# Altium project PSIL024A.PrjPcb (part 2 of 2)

## Sheet PSIL024A_sch3.SchDoc
size 431 x 279 mm; Date: Not shown in title block; ApprovedBy: Not shown in title block; CheckedBy: Not shown in title block; Author: Not shown in title block; CompanyName: Not shown in title block; Engineer: Not shown in title block; Organization: Not shown in title block; Address1: Not shown in title block; Address2: Not shown in title block; Address3: Not shown in title block; Address4: Not shown in title block; DocumentNumber: 1; Revision: Use project parameter SCH_Rev; SheetNumber: 3; SheetTotal: 4; PageSetup: Record=PageOptions¦CenterHorizontal=True¦CenterVertical=True¦PrintScale=1.00¦XCorrection=1.00¦YCorrection=1.00¦PrintKind=0¦BorderSize=5000000¦LeftOffset=0¦BottomOffset=0¦Orientation=2¦PaperLength=1000¦PaperWidth=1000¦Scale=100¦PaperSource=15¦PrintQuality=600¦MediaType=1¦DitherType=10¦PaperKind=Letter¦PrintScaleMode=1
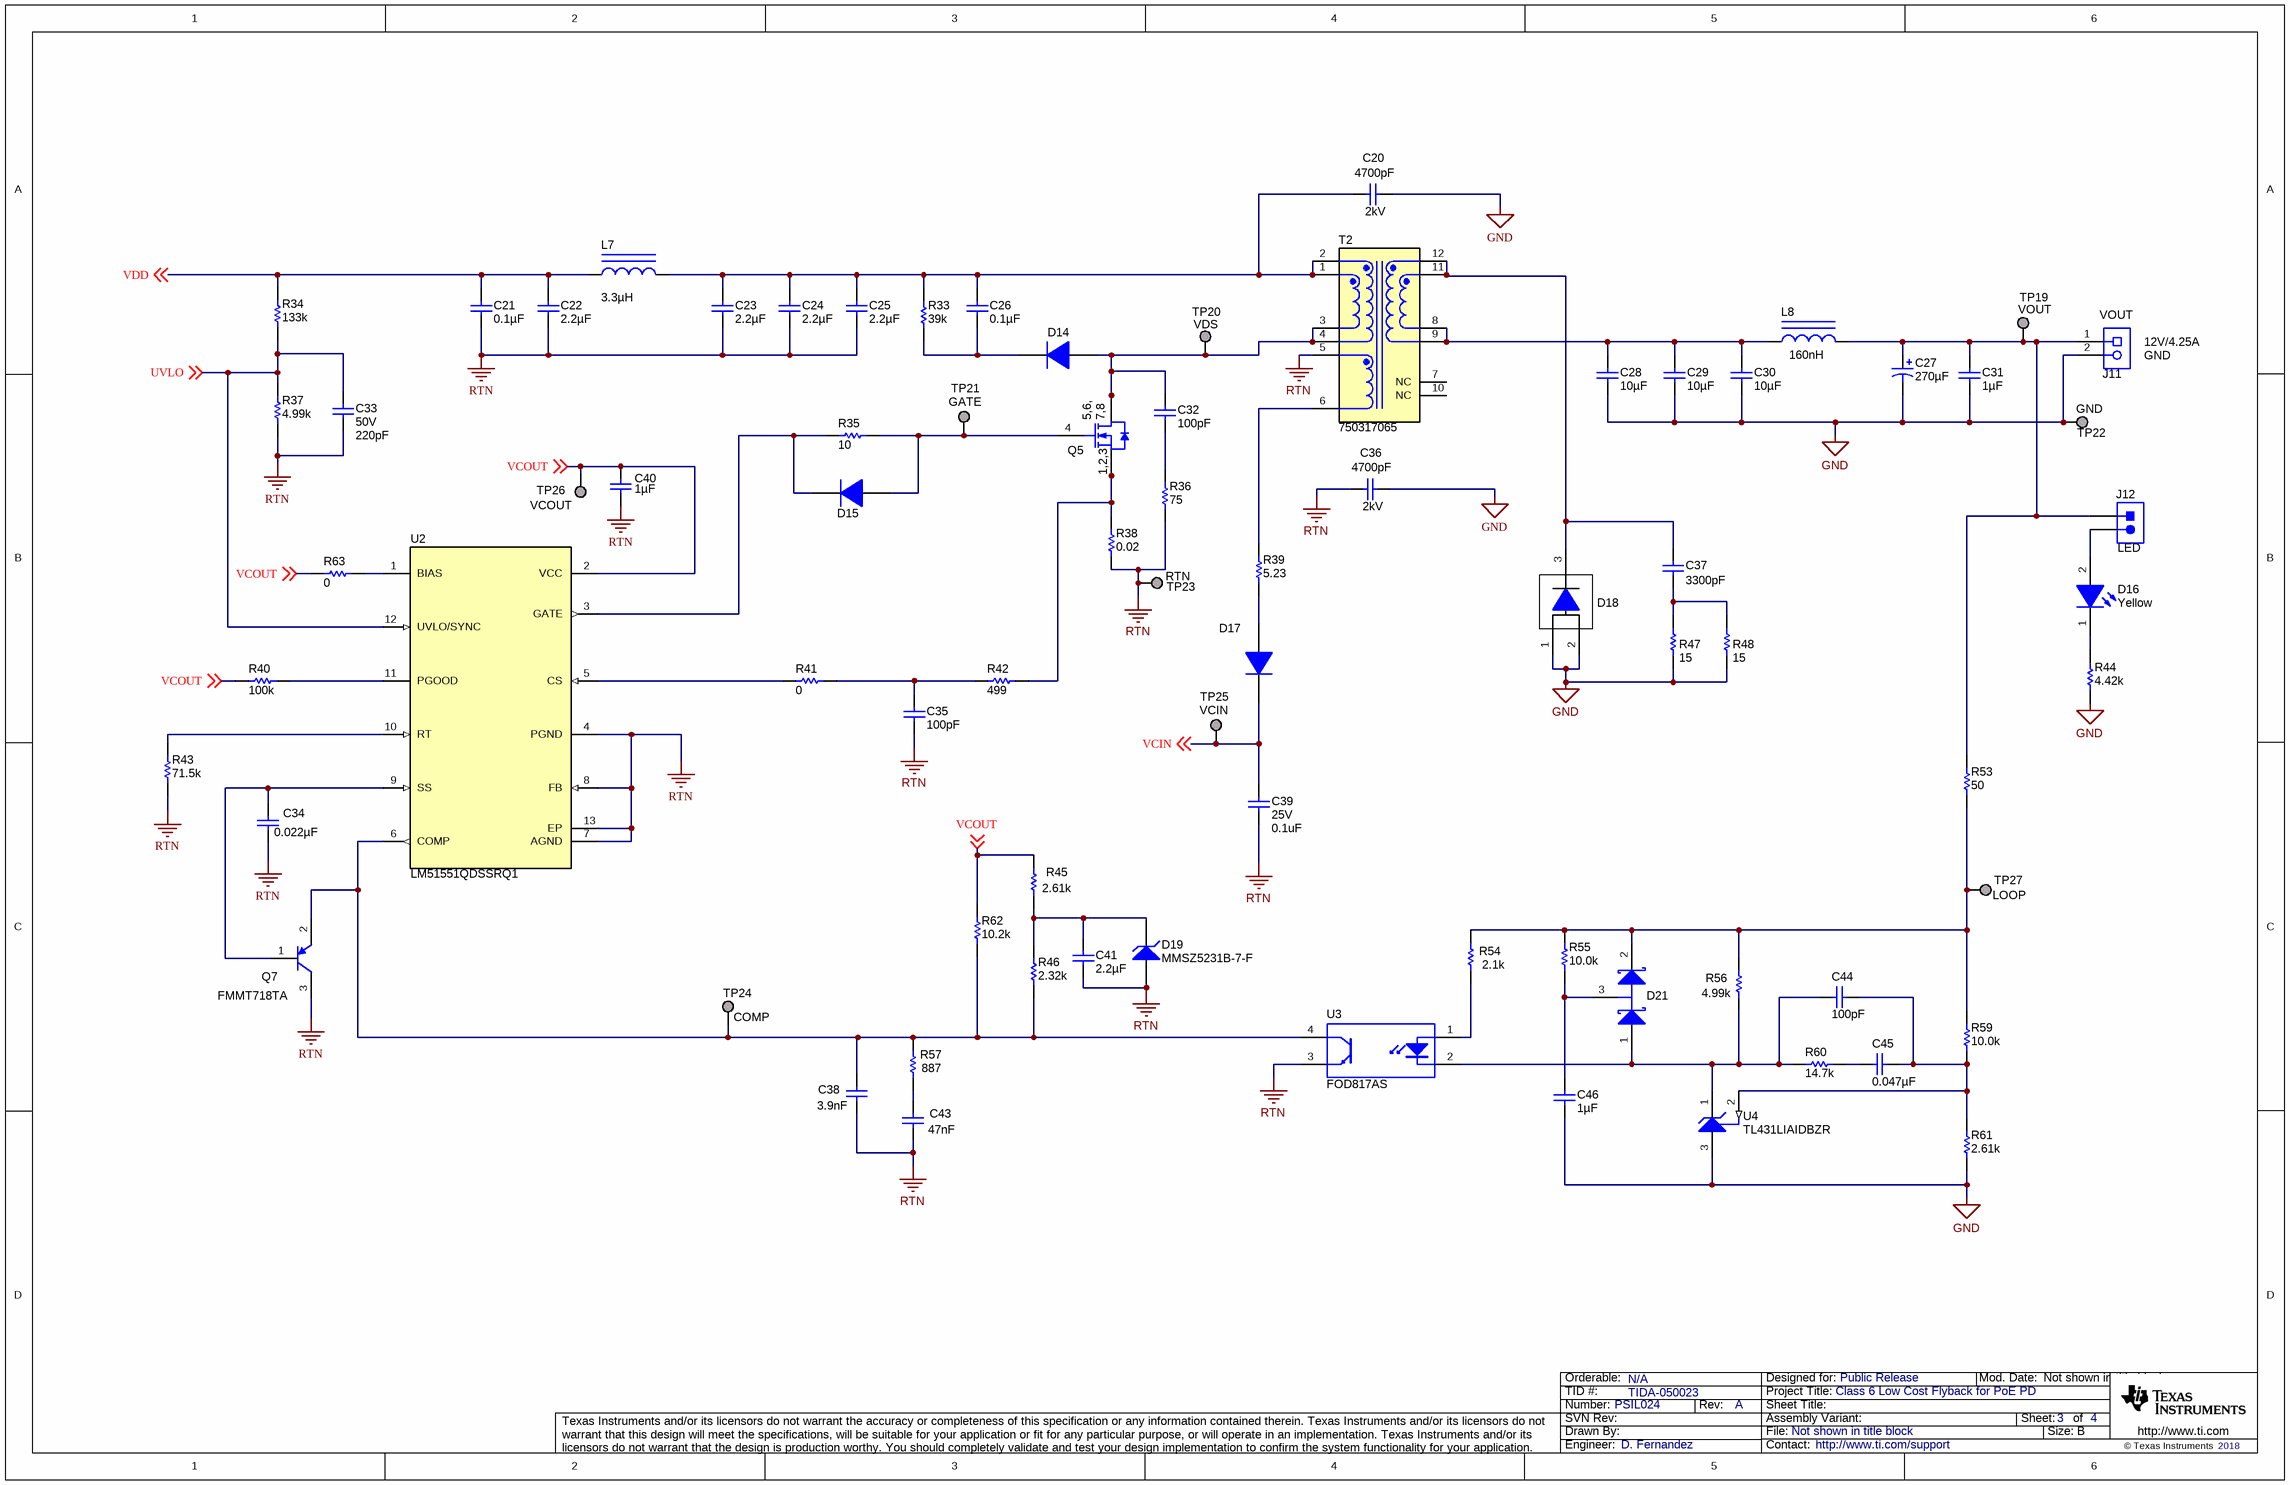
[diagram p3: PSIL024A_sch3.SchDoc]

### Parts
C20  VDC_V: 2kV  ValueDisplayed: 4700pF  [1812_254]  (hidden comment: 1812GC472KAT1A)
C21  ValueDisplayed: 0.1µF  [0805_HV]  (hidden comment: C2012X7R2A104K125AA)
C22  ValueDisplayed: 2.2µF  [1210_270]  (hidden comment: GRM32ER72A225KA35L)
C23  ValueDisplayed: 2.2µF  [1210_270]  (hidden comment: GRM32ER72A225KA35L)
C24  ValueDisplayed: 2.2µF  [1210_270]  (hidden comment: GRM32ER72A225KA35L)
C25  ValueDisplayed: 2.2µF  [1210_270]  (hidden comment: GRM32ER72A225KA35L)
C26  ValueDisplayed: 0.1µF  [0805_HV]  (hidden comment: C2012X7R2A104K125AA)
C27  ValueDisplayed: 270µF  [PCV_1000x1270]  (hidden comment: PCV1E271MCL1GS)
C28  ValueDisplayed: 10µF  [1210_280]  (hidden comment: C1210C106K3RACTU)
C29  ValueDisplayed: 10µF  [1210_280]  (hidden comment: C1210C106K3RACTU)
C30  ValueDisplayed: 10µF  [1210_280]  (hidden comment: C1210C106K3RACTU)
C31  ValueDisplayed: 1µF  [0805_HV]  (hidden comment: GRM21BR71E105KA99L)
C32  ValueDisplayed: 100pF  [0805_HV]  (hidden comment: GRM21A5C2E101JW01D)
C33  VDC_V: 50V  ValueDisplayed: 220pF  [0603L]  (hidden comment: C0603C221J5GACTU)
C34  ValueDisplayed: 0.022µF  [0603]  (hidden comment: C0603C223K3RACTU)
C35  ValueDisplayed: 100pF  [0603L]  (hidden comment: GRM1885C1H101JA01D)
C36  VDC_V: 2kV  ValueDisplayed: 4700pF  [1812_254]  (hidden comment: 1812GC472KAT1A)
C37  ValueDisplayed: 3300pF  [0603]  (hidden comment: 001)
C38  Cap_F: 3.9nF  [0603L]  (hidden comment: GRM1885C1H392JA01D)
C39  VDC_V: 25V  ValueDisplayed: 0.1uF  [0603]  (hidden comment: 06033C104JAT2A)
C40  ValueDisplayed: 1µF  [0805_HV]  (hidden comment: GRM21BR71E105KA99L)
C41  Cap_F: 2.2µF  [0603]  (hidden comment: EMK107BB7225KA-T)
C43  Cap_F: 47nF  [0603]  (hidden comment: 06033C473JAT2A)
C44  ValueDisplayed: 100pF  [0603L]  (hidden comment: GRM1885C1H101JA01D)
C45  ValueDisplayed: 0.047µF  [0603L]  (hidden comment: C1608X7R1H473K080AA)
C46  ValueDisplayed: 1µF  [0805L]  (hidden comment: GRM21BR71E105KA99L)
D14  ES2DA-13-F  [SMA]  (value not drawn)
D15  MMSD4148T1G  [SOD-123]  (value not drawn)
D16  value Yellow  [WL-SMCW_YELLOW]  (hidden comment: 150060YS75000)
D17  MMSD4148T1G  [SOD-123]  (value not drawn)
D18  001  [PowerDI5]  (value not drawn)
D19  MMSZ5231B-7-F  [SOD-123]
D21  BAT54S-7-F  [SOT-23]  (value not drawn)
J11  ED555/2DS  [TERM_BLK_ED555-2DS]  (value not drawn)
J12  LED  [Molex_87898-0204]
L7  ValueDisplayed: 3.3µH  [XFL4020]  (hidden comment: XFL4020-332MEB)
L8  Ind_H: 160nH  [XAL5030]  (hidden comment: XAL5030-161MEB)
Q5  FDMS86252  [TRANS_Fairchild_PQFN08A]  (value not drawn)
Q7  FMMT718TA  [SOT-23]
R33  ValueDisplayed: 39k  [1206]  (hidden comment: CRCW120639K0JNEA)
R34  133k  [0603]
R35  ValueDisplayed: 10  [0603]  (hidden comment: CRCW060310R0JNEA)
R36  ValueDisplayed: 75  [2010L]  (hidden comment: CRCW201075R0JNEF)
R37  ValueDisplayed: 4.99k  [0603]  (hidden comment: RT0603DRE074K99L)
R38  ValueDisplayed: 0.02  [2010]  (hidden comment: CSRN2010FK20L0)
R39  ValueDisplayed: 5.23  [0805_HV]  (hidden comment: CRCW08055R23FKEA)
R40  100k  [0603]
R41  ValueDisplayed: 0  [0603]  (hidden comment: MCR03EZPJ000)
R42  499  [0603]
R43  71.5k  [0603]
R44  ValueDisplayed: 4.42k  [0603]  (hidden comment: CRCW06034K42FKEA)
R45  Res_ohm: 2.61k  [0603]  (hidden comment: CRCW06032K61FKEA)
R46  Res_ohm: 2.32k  [0603]  (hidden comment: CRCW06032K32FKEA)
R47  ValueDisplayed: 15  [2512]  (hidden comment: 001)
R48  ValueDisplayed: 15  [2512]  (hidden comment: 001)
R53  ValueDisplayed: 50  [0603]  (hidden comment: CRCW060350R0FKEA)
R54  Res_ohm: 2.1k  [0603L]  (hidden comment: CRCW06032K10FKEA)
R55  ValueDisplayed: 10.0k  [0603L]  (hidden comment: CRCW060310K0FKEA)
R56  ValueDisplayed: 4.99k  [0603L]  (hidden comment: CRCW06034K99FKEA)
R57  Res_ohm: 887  [0603]  (hidden comment: CRCW0603887RFKEA)
R59  ValueDisplayed: 10.0k  [0603L]  (hidden comment: CRCW060310K0FKEA)
R60  ValueDisplayed: 14.7k  [0603]  (hidden comment: CRCW060314K7FKEA)
R61  ValueDisplayed: 2.61k  [0603L]  (hidden comment: CRCW06032K61FKEA)
R62  ValueDisplayed: 10.2k  [0603L]  (hidden comment: CRCW060310K2FKEA)
R63  ValueDisplayed: 0  [0603]  (hidden comment: MCR03EZPJ000)
T2  750317065  [Wurth_EFD25_4476]
TP19  VOUT  [Keystone_5019]
TP20  TESTPOINT  [Keystone_5019]  (value not drawn)
TP21  TESTPOINT  [Keystone_5019]  (value not drawn)
TP22  TESTPOINT  [Keystone_5019]  (value not drawn)
TP23  TESTPOINT  [Keystone_5019]  (value not drawn)
TP24  COMP  [Keystone_5019]
TP25  TESTPOINT  [Keystone_5019]  (value not drawn)
TP26  VCOUT  [Keystone_5019]
TP27  TESTPOINT  [Keystone_5019]  (value not drawn)
U2  LM51551QDSSRQ1  [DSS0012C]
U3  FOD817AS  [N04C]
U4  TL431LIAIDBZR  [DBZ0003A_M]

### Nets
GND: C20.1 C27.2(-) C28.2 C29.2 C30.2 C31.2 C36.1 C46.2 D18.1(A) D18.2(A) J11.2 R44.1 R47.1 R48.1 R61.1 TP22.1 U4.3(ANODE)
RTN: C21.1 C22.2 C23.2 C24.2 C25.2 C33.2 C34.2 C35.2 C36.2 C38.2 C39.2 C40.2 C41.2 C43.2 D19.2(A) Q7.3(C) R36.1 R37.1 R38.1 R43.1 T2.5 TP23.1 U2.4(PGND) U2.7(AGND) U2.8(FB) U2.13(EP) U3.3(E)
UVLO: C33.1 R34.1 R37.2 U2.12(UVLO/SYNC) ; off-sheet UVLO
VCIN: C39.1 D17.1(K) TP25.1 ; off-sheet VCIN
VCOUT: C40.1 R40.1 R45.2 R62.2 R63.1 TP26.1 U2.2(VCC) ; off-sheet VCOUT
VDD: C21.2 C22.1 L7.1 R34.2 ; off-sheet VDD
NetC20_2: C20.2 C23.1 C24.1 C25.1 C26.2 L7.2 R33.2 T2.1 T2.2
NetC26_1: C26.1 D14.1(K) R33.1
NetC27_1: C27.1(+) C31.1 J11.1 J12.1 L8.2 R53.2 TP19.1
NetC28_1: C28.1 C29.1 C30.1 L8.1 T2.8 T2.9
NetC32_1: C32.1 D14.2(A) Q5.5(D) Q5.6(D) Q5.7(D) Q5.8(D) T2.3 T2.4 TP20.1
NetC32_2: C32.2 R36.2
NetC34_1: C34.1 Q7.1(B) U2.9(SS)
NetC35_1: C35.1 R41.2 R42.1
NetC37_1: C37.1 D18.3(K) T2.11 T2.12
NetC37_2: C37.2 R47.2 R48.2
NetC38_1: C38.1 Q7.2(E) R46.1 R57.2 R62.1 TP24.1 U2.6(COMP) U3.4(C)
NetC41_1: C41.1 D19.1(K) R45.1 R46.2
NetC43_1: C43.1 R57.1
NetC44_1: C44.1 C45.1 R59.1 R61.2 U4.2(REF)
NetC44_2: C44.2 D21.1(A) R56.1 R60.1 U3.2(K) U4.1(CATHODE)
NetC45_2: C45.2 R60.2
NetC46_1: C46.1 D21.3(C) R55.1
NetD15_1: D15.1(K) R35.1 U2.3(GATE)
NetD15_2: D15.2(A) Q5.4(G) R35.2 TP21.1
NetD16_1: D16.1(K) R44.2
NetD16_2: D16.2(A) J12.2
NetD17_2: D17.2(A) R39.1
NetD21_2: D21.2(K) R53.1 R54.2 R55.2 R56.2 R59.2 TP27.1
NetQ5_1: Q5.1(S) Q5.2(S) Q5.3(S) R38.2 R42.2
NetR39_2: R39.2 T2.6
NetR40_2: R40.2 U2.11(PGOOD)
NetR41_1: R41.1 U2.5(CS)
NetR43_2: R43.2 U2.10(RT)
NetR54_1: R54.1 U3.1(A)
NetR63_2: R63.2 U2.1(BIAS)

Not connected (* = marked no-connect by the designer): T2 7(NC) 10(NC)

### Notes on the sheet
- (near TP20) VDS
- (near J11) VOUT
- (near J11) 12V/4.25A
- (near J11) GND
- (near TP21) GATE
- (near TP22) GND
- (near TP23) RTN
- (near TP25) VCIN
- (near TP27) LOOP

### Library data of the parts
C20 C36 = CMP-0009295-2: CAP, CERM, 4700 pF, 2000 V, +/- 10%, X7R, 1812; Manufacturer: AVX; TaMin_C: -55°C; Polarized: N; SizeAreaWB_mm2: 23.1; Value1: Unknown; U/M: EA; Value: 4700pF; TaMax_C: 125°C; SizeZ_mm: 2.54; SizeX_mm: 4.5; SizeY_mm: 3.2; Cap_Case: 1812; Value2: 2000V; SizeArea_mm2: 14.4; Cap_F: 4.7nF; AEC Category: Q200
C21 C26 = C2012X7R2A104K125AA: CAP, CERM, 0.1 µF, 100 V, +/- 10%, X7R, 0805; Manufacturer: TDK; Polarized: N; CompType: Capacitor; Value: 0.1uF; U/M: EA; Cap_F: 0.0000001; Tolerance_%: 10; ESR_ohm: 0.020726; Value1: 0.020726 ohm; VDC_V: 100; Value2: 100V; IRMS_A: 1.456; TaMin_C: -55; TaMax_C: 125; Cap_Case: 0805; SizeArea_mm2: 2.5; SizeAreaWB_mm2: 6.75; SizeX_mm: 2; SizeY_mm: 1.25; SizeZ_mm: 1.45; AEC Category: Q200
C22-C25 = GRM32ER72A225KA35L: CAP, CERM, 2.2 µF, 100 V, +/- 10%, X7R, 1210; Manufacturer: MuRata; Polarized: N; CompType: Capacitor; Value: 2.2uF; U/M: EA; Cap_F: 0.0000022; Tolerance_%: 10; ESR_ohm: 0.007; Value1: 0.007 ohm; VDC_V: 100; Value2: 100V; IRMS_A: 4.4; TaMin_C: -55; TaMax_C: 125; Cap_Case: 1210; SizeArea_mm2: 8; SizeAreaWB_mm2: 14.7; SizeX_mm: 3.2; SizeY_mm: 2.5; SizeZ_mm: 2.7; AEC Category: Q200
C27 = PCV1E271MCL1GS: CAP, Aluminum Polymer, 270 µF, 25 V,+/- 20%, 0.027 ohm, D10xL12.7mm SMD; Manufacturer: Nichicon; Polarized: Y; CompType: Capacitor; Value: 270uF; U/M: EA; Cap_F: 0.00027; Tolerance_%: 20; VDC_V: 25; Value2: 25V; ESR_ohm: 0.027; IRMS_A: 2.7; TaMin_C: -55; TaMax_C: 105; Cap_Case: 10x12.7mm; SizeAreaWB_mm2: 144; SizeArea_mm2: 100; SizeX_mm: 10; SizeZ_mm: 12.7; AEC Category: Q200; AEC Qualified: N; Green_Lifecycle: Active; Green_REACh: Passed
C28-C30 = C1210C106K3RACTU: CAP, CERM, 10 µF, 25 V, +/- 10%, X7R, 1210; Manufacturer: Kemet; Polarized: N; CompType: Capacitor; Value: 10uF; U/M: EA; Cap_F: 0.00001; Tolerance_%: 10; Value1: Unknown; VDC_V: 25; Value2: 25V; TaMin_C: -55; TaMax_C: 125; Cap_Case: 1210; SizeArea_mm2: 8; SizeAreaWB_mm2: 14.7; SizeX_mm: 3.2; SizeY_mm: 2.5; SizeZ_mm: 2.8; AEC Category: Q200
C31 C40 C46 = GRM21BR71E105KA99L: CAP, CERM, 1 µF, 25 V, +/- 10%, X7R, 0805; Manufacturer: MuRata; Polarized: N; CompType: Capacitor; Value: 1uF; U/M: EA; Cap_F: 0.000001; Tolerance_%: 10; Value1: Unknown; VDC_V: 25; Value2: 25V; TaMin_C: -55; TaMax_C: 125; Cap_Case: 0805; SizeArea_mm2: 2.5; SizeAreaWB_mm2: 6.75; SizeX_mm: 2; SizeY_mm: 1.25; SizeZ_mm: 1.45; AEC Category: Q200
C32 = GRM21A5C2E101JW01D: CAP, CERM, 100 pF, 250 V, +/- 5%, C0G/NP0, 0805; Manufacturer: MuRata; Polarized: N; CompType: Capacitor; Value: 100pF; U/M: EA; Cap_F: 0.0000000001; Tolerance_%: 5; Value1: Unknown; VDC_V: 250; Value2: 250V; TaMin_C: -55; TaMax_C: 125; Cap_Case: 0805; SizeArea_mm2: 2.5; SizeAreaWB_mm2: 6.75; SizeX_mm: 2; SizeY_mm: 1.25; SizeZ_mm: 1.45; AEC Category: Q200
C33 = CMP-0006893-4: CAP, CERM, 220 pF, 50 V, +/- 5%, C0G/NP0, 0603; Manufacturer: Kemet; TaMin_C: -55°C; Polarized: N; SizeAreaWB_mm2: 4.68; Value1: Unknown; U/M: EA; Value: 220pF; TaMax_C: 125°C; SizeZ_mm: 1; SizeX_mm: 1.6; SizeY_mm: 0.8; Cap_Case: 0603; SizeArea_mm2: 1.28; CompType: Capacitor; AEC Category: Q200
C34 = C0603C223K3RACTU: CAP, CERM, 0.022 µF, 25 V,+/- 10%, X7R, 0603; Manufacturer: Kemet; Polarized: N; CompType: Capacitor; Value: 0.022uF; U/M: EA; Cap_F: 0.000000022; Tolerance_%: 10; VDC_V: 25; Value2: 25V; TaMin_C: -55; TaMax_C: 125; SizeArea_mm2: 1.28; SizeAreaWB_mm2: 4.68; SizeX_mm: 1.6; SizeY_mm: 0.8; SizeZ_mm: 1; AEC Category: Q200; Green_Lifecycle: Active; Green_REACh: Passed
C35 C44 = GRM1885C1H101JA01D: CAP, CERM, 100 pF, 50 V, +/- 5%, C0G/NP0, 0603; Manufacturer: MuRata; Polarized: N; CompType: Capacitor; Value: 100pF; U/M: EA; Cap_F: 0.0000000001; Tolerance_%: 5; Value1: Unknown; VDC_V: 50; Value2: 50V; TaMin_C: -55; TaMax_C: 125; Cap_Case: 0603; SizeArea_mm2: 1.28; SizeAreaWB_mm2: 4.68; SizeX_mm: 1.6; SizeY_mm: 0.8; SizeZ_mm: 1; AEC Category: Q200
C37 = GRM188R72A332KA01D: CAP, CERM, 3300 pF, 100 V, +/- 10%, X7R, 0603; Manufacturer: MuRata; Polarized: N; CompType: Capacitor; Value: 3300pF; U/M: EA; Cap_F: 0.0000000033; Tolerance_%: 10; Value1: Unknown; VDC_V: 100; Value2: 100V; TaMin_C: -55; TaMax_C: 125; SizeArea_mm2: 1.28; SizeAreaWB_mm2: 4.68; SizeX_mm: 1.6; SizeY_mm: 0.8; SizeZ_mm: 1; AEC Category: Q200
C38 = CMP-0007216-4: CAP, CERM, 3900 pF, 50 V, +/- 5%, C0G/NP0, 0603; Manufacturer: MuRata; TaMin_C: -55°C; Polarized: N; SizeAreaWB_mm2: 4.68; Value1: Unknown; U/M: EA; Value: 3900pF; TaMax_C: 125°C; SizeZ_mm: 1; SizeX_mm: 1.6; SizeY_mm: 0.8; Cap_Case: 0603; Value2: 50V; SizeArea_mm2: 1.28; CompType: Capacitor; AEC Category: Q200
C39 = CMP-0006752-5: CAP, CERM, 0.1 uF, 25 V, +/- 5%, X7R, 0603; Manufacturer: AVX; TaMin_C: -55°C; ESR_ohm: 0.05; Polarized: N; SizeAreaWB_mm2: 4.68; Value1: 0.05 ohm; U/M: EA; Value: 0.1uF; TaMax_C: 125°C; SizeZ_mm: 1; SizeX_mm: 1.6; SizeY_mm: 0.8; SizeArea_mm2: 1.28; Cap_F: 100nF; AEC Category: Q200
C41 = CMP-0007121-4: CAP, CERM, 2.2 uF, 16 V, +/- 10%, X7R, 0603; Manufacturer: Taiyo Yuden; TaMin_C: -55°C; Polarized: N; SizeAreaWB_mm2: 4.68; Value1: Unknown; U/M: EA; Value: 2.2uF; TaMax_C: 125°C; SizeZ_mm: 1; SizeX_mm: 1.6; SizeY_mm: 0.8; Value2: 16V; SizeArea_mm2: 1.28; CompType: Capacitor; AEC Category: Q200
C43 = CMP-0006757-5: CAP, CERM, 0.047 uF, 25 V, +/- 5%, X7R, 0603; Manufacturer: AVX; Polarized: N; CompType: Capacitor; U/M: EA; ESR_ohm: 0.052; Value1: 0.052 ohm; VDC_V: 25V; TaMin_C: -55°C; TaMax_C: 125°C; SizeArea_mm2: 1.28; SizeAreaWB_mm2: 4.68; SizeX_mm: 1.6; SizeY_mm: 0.8; SizeZ_mm: 1; AEC Category: Q200
C45 = C1608X7R1H473K080AA: CAP, CERM, 0.047 µF, 50 V, +/- 10%, X7R, 0603; Manufacturer: TDK; Polarized: N; CompType: Capacitor; Value: 0.047uF; U/M: EA; Cap_F: 0.000000047; Tolerance_%: 10; ESR_ohm: 0.049007; Value1: 0.049007 ohm; VDC_V: 50; Value2: 50V; IRMS_A: 0.767528; TaMin_C: -55; TaMax_C: 125; Cap_Case: 0603; SizeArea_mm2: 1.28; SizeAreaWB_mm2: 4.68; SizeX_mm: 1.6; SizeY_mm: 0.8; SizeZ_mm: 1; AEC Category: Q200
D14 = ES2DA-13-F: Diode, Superfast Rectifier, 200 V, 2 A, SMA; Manufacturer: Diodes Inc.; U/M: EA; Vf_V: 0.92; Value: 200V; Value1: 2A; Value2: 0.92V; Io_A: 2; Vr_V: 200; TJmax_C: 150; RJC_CperW: 20; SizeAreaWB_mm2: 37.3428; SizeArea_mm2: 16.3228; SizeX_mm: 5.59; SizeY_mm: 2.92; SizeZ_mm: 2.87; AEC Category: Q101
D15 D17 = MMSD4148T1G: Diode, Switching, 100 V, 0.2 A, SOD-123; Manufacturer: ON Semiconductor; U/M: EA; Vf_V: 1; Value: 100V; Value1: 0.2A; Value2: 1V; Io_A: 0.2; Vr_V: 100; TJmax_C: 150; SizeAreaWB_mm2: 13.095; SizeArea_mm2: 6.545; SizeX_mm: 3.85; SizeY_mm: 1.7; SizeZ_mm: 1.35; AEC Category: Q101
D16 = 150060YS75000: LED, Yellow, SMD; Manufacturer: Wurth Elektronik; Type: AlInGaP; Vf_V: 2; Value2: 2V; Io_A: 0.02; Value1: W; U/M: EA; Green_Lifecycle: Active; Green_REACh: Passed
D18 = SBRT20U60SP5-7: Diode, Super Barrier Rectifier, 60 V, 20 A, AEC-Q101, PowerDI5; Manufacturer: Diodes Inc.; SymbolCreator: a0412235; U/M: EA; Vf_V: 0.53; Value: 60V; Value1: 20A; Value2: 0.53V; Io_A: 20; Vr_V: 60; TJmax_C: 150; SizeAreaWB_mm2: 49.56; SizeArea_mm2: 24.96; SizeX_mm: 6.4; SizeY_mm: 3.9; SizeZ_mm: 1.05; AEC Category: Q101; AEC Qualified: Y; Green_Lifecycle: Not Set; Green_REACh: Incomplete
D19 = CMP-0005802-3: Diode, Zener, 5.1 V, 500 mW, SOD-123; Manufacturer: Diodes Inc.; SizeAreaWB_mm2: 13.095; SizeX_mm: 3.85; SizeArea_mm2: 6.545; Power_W: 500mW; Vz_V: 5.1V; RJA_CperW: 350; AEC Category: Q101; SizeY_mm: 1.7; Value1: 0.5W; Value: 5.1V; SizeZ_mm: 1.35
D21 = BAT54S-7-F: Diode, Schottky, 30 V, 0.2 A, SOT-23; Manufacturer: Diodes Inc.; U/M: EA; Vf_V: 0.65; Value: 30V; Value1: 0.2A; Value2: 0.65V; Io_A: 0.2; Vr_V: 30; TJmax_C: 125; SizeAreaWB_mm2: 14; SizeArea_mm2: 7.5; SizeX_mm: 2.5; SizeY_mm: 3; SizeZ_mm: 1.1; AEC Category: Q101
J11 = ED555/2DS: Terminal Block, 3.5mm Pitch, 2x1, TH; Manufacturer: On-Shore Technology; SymbolCreator: a0412235; Pitch_mm: 3.5; Gender: Female; Shrouded: N; Row_Count: 1; ContactFinish: Brass; Current_A: 6; Voltage_V: 150; Cert_CULUS: Y
J12 = 87898-0204: Header, 2.54 mm, 2x1, Gold, R/A, SMT; Manufacturer: Molex; SymbolCreator: a0412235; Pitch_mm: 2.54; Gender: Male; Shrouded: N; Row_Count: 1
L7 = XFL4020-332MEB: Inductor, Shielded, Composite, 3.3 µH, 2.9 A, 0.03 ohm, SMD; Manufacturer: Coilcraft; Value: 3.3uH; Ind_H: 3.3E-6; Imax_A: 2.9; Irms: 5.2A @ 40C rise; Isat: 2.9A @ 30% inductance drop; DCR_ohm: 0.03; Value2: 2.9A; AEC Category: Q200
L8 = CMP-0061000-2: Inductor, Shielded, Composite, 160 nH, 22.2 A, 0.00215 ohm, AEC-Q200 Grade 1, SMD; Manufacturer: Coilcraft; Isat: 31A @ 30% inductance drop; Irms: 22.2A @ 40C rise; Green_Lifecycle: Not Set; SizeAreaWB_mm2: 54.4544; DCR_ohm: 2.15m; Green_REACh: Incomplete; Value: 160nH; Imax_A: 22.2A; SizeZ_mm: 3.1; SizeX_mm: 5.28; SizeY_mm: 5.48; SizeArea_mm2: 28.9344; AEC Qualified: 1; AEC Category: Q200; AEC Grade: Y
Q5 = FDMS86252: MOSFET, N-CH, 150 V, 4.6 A, PQFN08A; Manufacturer: Fairchild Semiconductor; Alternate Manufacturer: None; U/M: EA; ChType: N; Value: 150V; VdsMax_V: 150; Value1: 0.07 ohm; Rdson45_ohm: 0.07; Value2: 11 nC; QgTyp_nC: 11; Vgs_V: 20; IdsMax_A: 4.6; SizeAreaWB_mm2: 56; SizeArea_mm2: 30; SizeX_mm: 5; SizeY_mm: 6; SizeZ_mm: 1.1; AEC Category: Q101
Q7 = CMP-0000330-2: Transistor, PNP, 20 V, 1.5 A, SOT-23; Manufacturer: Diodes Inc.; TaMax_C: 150°C; Value2: 6; Value1: 1.5 A; Vcesat1_V: 20V; SizeX_mm: 2.5; SizeY_mm: 3; TaMin_C: -55°C; IcRated_A: 1.5A; CompType: BJT; SizeZ_mm: 1.1; Value: 20 V; SizeArea_mm2: 7.5; NPN: 0; PNP: 1; AEC Category: Q101; SizeAreaWB_mm2: 14; U/M: EA
R33 = CRCW120639K0JNEA: RES, 39 k, 5%, 0.25 W, 1206; Manufacturer: Vishay-Dale; CompType: Resistor; Value: 39k; Res_ohm: 39000; Value_Code: 39k0; Tolerance_%: 5; Power_W: 0.25; Value2: 0.25W; VDC_V: 200; TempCo: 200 ppm/C; SizeArea_mm2: 5.12; SizeX_mm: 3.2; SizeY_mm: 1.6; SizeZ_mm: 1.35; EIA_Code: E24; U/M: EA; AEC Category: Q200
R34 = CMP-0024655-3: RES, 133 k, 0.5%, 0.1 W, 0603; Manufacturer: Yageo America; PartNumber: RT0603DRE07133KL; Power_W: 100mW; TempCo: 50 ppm/C; U/M: EA; EIA_Code: E192; SizeX_mm: 1.6; SizeY_mm: 0.8; SizeZ_mm: 1; Value2: 0.1W; SizeArea_mm2: 1.28; CompType: Resistor; VDC_V: 75V; AEC Category: Q200
R35 = CMP-0025703-4: RES, 10, 5%, 0.1 W, AEC-Q200 Grade 0, 0603; Manufacturer: Vishay-Dale; Value: 10; Value_Code: 10R0; Power_W: 100mW; Value2: 0.1W; VDC_V: 75V; TempCo: 200 ppm/C; SizeArea_mm2: 1.28; SizeX_mm: 1.6; SizeY_mm: 0.8; SizeZ_mm: 1; EIA_Code: E24; AEC Category: Q200; AEC Qualified: Y; AEC Grade: 0
R36 = CRCW201075R0JNEF: RES, 75, 5%, 0.75 W, AEC-Q200 Grade 0, 2010; Manufacturer: Vishay-Dale; CompType: Resistor; Value: 75; Value_Code: 75R0; Tolerance_%: 5; Power_W: 0.75; Value2: 0.75W; VDC_V: 400; TempCo: 200 ppm/C; SizeArea_mm2: 12.5; SizeY_mm: 2.5; SizeZ_mm: 1.66; EIA_Code: E24; U/M: EA; AEC Category: Q200; AEC Qualified: Y; AEC Grade: 0
R37 = RT0603DRE074K99L: RES, 4.99 k, 0.5%, 0.1 W, 0603; Manufacturer: Yageo America; CompType: Resistor; Value: 4.99k; Res_ohm: 4990; Value_Code: 4k99; Tolerance_%: 0.5; Power_W: 0.1; Value2: 0.1W; VDC_V: 75; TempCo: 50 ppm/C; SizeArea_mm2: 1.28; SizeX_mm: 1.6; SizeY_mm: 0.8; SizeZ_mm: 1; EIA_Code: E192; U/M: EA; AEC Category: Q200; Green_Lifecycle: Active; Green_REACh: Passed
R38 = CSRN2010FK20L0: RES, 0.02, 1%, 1 W, 2010; Manufacturer: Stackpole Electronics Inc; CompType: Resistor; Value: 0.02; Value_Code: R020; Tolerance_%: 1; Value2: 1W; TempCo: 250 ppm/C; SizeArea_mm2: 12.5; SizeX_mm: 5; SizeY_mm: 2.5; SizeZ_mm: 1.66; EIA_Code: E96; U/M: EA; AEC Category: Q200
R39 = CRCW08055R23FKEA: RES, 5.23, 1%, 0.125 W, 0805; Manufacturer: Vishay-Dale; CompType: Resistor; Value: 5.23; Value_Code: 5R23; Tolerance_%: 1; Power_W: 0.125; Value2: 0.125W; VDC_V: 150; TempCo: 100 ppm/C; SizeArea_mm2: 2.5; SizeX_mm: 2; SizeY_mm: 1.25; SizeZ_mm: 1.45; EIA_Code: E96; U/M: EA; AEC Category: Q200
R40 = CMP-0021990-4: RES, 100 k, 1%, 0.1 W, AEC-Q200 Grade 0, 0603; Manufacturer: Vishay-Dale; PartNumber: CRCW0603100KFKEA; Power_W: 100mW; TempCo: 100 ppm/C; EIA_Code: E96; SizeX_mm: 1.6; SizeY_mm: 0.8; SizeZ_mm: 1; Value2: 0.1W; SizeArea_mm2: 1.28; CompType: Resistor; AEC Qualified: Y; VDC_V: 75V; AEC Category: Q200; AEC Grade: 0
R41 R63 = MCR03EZPJ000: RES, 0, 5%, 0.1 W, 0603; Manufacturer: Rohm; CompType: Resistor; Value: 0; Value_Code: 0000; Tolerance_%: 5; Power_W: 0.1; Value2: 0.1W; VDC_V: 50; TempCo: 400 ppm/C; SizeArea_mm2: 1.28; SizeX_mm: 1.6; SizeY_mm: 0.8; SizeZ_mm: 1; EIA_Code: E24; U/M: EA; AEC Category: Q200; AEC Qualified: N; Green_Lifecycle: Active; Green_REACh: Passed
R42 = CMP-0025330-3: RES, 499, 0.5%, 0.1 W, 0603; Manufacturer: Yageo America; PartNumber: RT0603DRE07499RL; Power_W: 100mW; TempCo: 50 ppm/C; Value_Code: 499R; U/M: EA; EIA_Code: E192; SizeX_mm: 1.6; SizeY_mm: 0.8; SizeZ_mm: 1; Value2: 0.1W; SizeArea_mm2: 1.28; CompType: Resistor; VDC_V: 75V; AEC Category: Q200
R43 = CMP-0025543-3: RES, 71.5 k, 0.5%, 0.1 W, 0603; Manufacturer: Yageo America; PartNumber: RT0603DRE0771K5L; Power_W: 100mW; TempCo: 50 ppm/C; Value_Code: 71k5; U/M: EA; EIA_Code: E192; SizeX_mm: 1.6; SizeY_mm: 0.8; SizeZ_mm: 1; Value2: 0.1W; SizeArea_mm2: 1.28; CompType: Resistor; VDC_V: 75V; AEC Category: Q200
R44 = CRCW06034K42FKEA: RES, 4.42 k, 1%, 0.1 W, 0603; Manufacturer: Vishay-Dale; CompType: Resistor; Value: 4.42k; Res_ohm: 4420; Value_Code: 4k42; Tolerance_%: 1; Power_W: 0.1; Value2: 0.1W; VDC_V: 75; TempCo: 100 ppm/C; SizeArea_mm2: 1.28; SizeX_mm: 1.6; SizeY_mm: 0.8; EIA_Code: E96; U/M: EA; AEC Category: Q200; Green_Lifecycle: Active; Green_REACh: Passed
R45 = CMP-0022279-4: RES, 2.61 k, 1%, 0.1 W, AEC-Q200 Grade 0, 0603; Manufacturer: Vishay-Dale; Power_W: 100mW; TempCo: 100 ppm/C; Value_Code: 2k61; Value: 2.61k; EIA_Code: E96; SizeX_mm: 1.6; SizeY_mm: 0.8; SizeZ_mm: 1; Value2: 0.1W; SizeArea_mm2: 1.28; CompType: Resistor; AEC Qualified: Y; VDC_V: 75V; AEC Category: Q200; AEC Grade: 0
R46 = CMP-0022274-4: RES, 2.32 k, 1%, 0.1 W, AEC-Q200 Grade 0, 0603; Manufacturer: Vishay-Dale; Power_W: 100mW; TempCo: 100 ppm/C; Value_Code: 2k32; Value: 2.32k; EIA_Code: E96; SizeX_mm: 1.6; SizeY_mm: 0.8; SizeZ_mm: 1; Value2: 0.1W; SizeArea_mm2: 1.28; CompType: Resistor; AEC Qualified: Y; VDC_V: 75V; AEC Category: Q200; AEC Grade: 0
R47 R48 = CRCW251215R0JNEG: RES, 15, 5%, 1 W, AEC-Q200 Grade 0, 2512; Manufacturer: Vishay-Dale; CompType: Resistor; Value: 15; Value_Code: 15R0; Tolerance_%: 5; Power_W: 1; Value2: 1W; VDC_V: 500; TempCo: 200 ppm/C; EIA_Code: E24; U/M: EA; SizeArea_mm2: 20.16; SizeX_mm: 6.3; SizeY_mm: 3.2; SizeZ_mm: 0.71; AEC Category: Q200; AEC Qualified: Y; AEC Grade: 0
R53 = CRCW060350R0FKEA: RES, 50, 1%, 0.1 W, 0603; Manufacturer: Vishay-Dale; CompType: Resistor; Value: 50; Value_Code: 50R0; Tolerance_%: 1; Power_W: 0.1; Value2: 0.1W; VDC_V: 75; TempCo: 100 ppm/C; SizeArea_mm2: 1.28; SizeX_mm: 1.6; SizeY_mm: 0.8; U/M: EA; AEC Category: Q200; Green_Lifecycle: Active; Green_REACh: Passed
R54 = CMP-0022270-4: RES, 2.10 k, 1%, 0.1 W, AEC-Q200 Grade 0, 0603; Manufacturer: Vishay-Dale; CompType: Resistor; Value: 2.10k; Value_Code: 2k10; Power_W: 100mW; Value2: 0.1W; VDC_V: 75V; TempCo: 100 ppm/C; SizeArea_mm2: 1.28; SizeX_mm: 1.6; SizeY_mm: 0.8; SizeZ_mm: 1; EIA_Code: E96; AEC Category: Q200; AEC Qualified: Y; AEC Grade: 0
R55 R59 = CRCW060310K0FKEA: RES, 10.0 k, 1%, 0.1 W, 0603; Manufacturer: Vishay-Dale; CompType: Resistor; Value: 10.0k; Res_ohm: 10000; Value_Code: 10k0; Tolerance_%: 1; Power_W: 0.1; Value2: 0.1W; VDC_V: 75; TempCo: 100 ppm/C; SizeArea_mm2: 1.28; SizeX_mm: 1.6; SizeY_mm: 0.8; EIA_Code: E96; U/M: EA; AEC Category: Q200
R56 = CRCW06034K99FKEA: RES, 4.99 k, 1%, 0.1 W, 0603; Manufacturer: Vishay-Dale; CompType: Resistor; Value: 4.99k; Res_ohm: 4990; Value_Code: 4k99; Tolerance_%: 1; Power_W: 0.1; Value2: 0.1W; VDC_V: 75; TempCo: 100 ppm/C; SizeArea_mm2: 1.28; SizeX_mm: 1.6; SizeY_mm: 0.8; EIA_Code: E96; U/M: EA; AEC Category: Q200
R57 = CMP-0022631-5: RES, 887, 1%, 0.1 W, AEC-Q200 Grade 0, 0603; Manufacturer: Vishay-Dale; CompType: Resistor; Value: 887; Value_Code: 887R; Power_W: 100mW; Value2: 0.1W; VDC_V: 75V; TempCo: 100 ppm/C; SizeArea_mm2: 1.28; SizeX_mm: 1.6; SizeY_mm: 0.8; SizeZ_mm: 1; EIA_Code: E96; AEC Category: Q200; AEC Qualified: Y; AEC Grade: 0
R60 = CRCW060314K7FKEA: RES, 14.7 k, 1%, 0.1 W, 0603; Manufacturer: Vishay-Dale; CompType: Resistor; Value: 14.7k; Res_ohm: 14700; Value_Code: 14k7; Tolerance_%: 1; Power_W: 0.1; Value2: 0.1W; VDC_V: 75; TempCo: 100 ppm/C; SizeArea_mm2: 1.28; SizeX_mm: 1.6; SizeY_mm: 0.8; EIA_Code: E96; U/M: EA; AEC Category: Q200; Green_Lifecycle: Active; Green_REACh: Passed
R61 = CRCW06032K61FKEA: RES, 2.61 k, 1%, 0.1 W, 0603; Manufacturer: Vishay-Dale; CompType: Resistor; Value: 2.61k; Res_ohm: 2610; Value_Code: 2k61; Tolerance_%: 1; Power_W: 0.1; Value2: 0.1W; VDC_V: 75; TempCo: 100 ppm/C; SizeArea_mm2: 1.28; SizeX_mm: 1.6; SizeY_mm: 0.8; EIA_Code: E96; U/M: EA; AEC Category: Q200
R62 = CMP-0021999-4: RES, 10.2 k, 1%, 0.1 W, AEC-Q200 Grade 0, 0603; Manufacturer: Vishay-Dale; Power_W: 100mW; TempCo: 100 ppm/C; Value_Code: 10k2; Value: 10.2k; EIA_Code: E96; SizeX_mm: 1.6; SizeY_mm: 0.8; SizeZ_mm: 1; Value2: 0.1W; SizeArea_mm2: 1.28; AEC Qualified: Y; VDC_V: 75V; AEC Category: Q200; AEC Grade: 0
T2 = CMP-0077631-2: Transformer, 30 uH, SMT; Manufacturer: Wurth Elektronik; SizeAreaWB_mm2: 1000.0835; SizeArea_mm2: 877.1235; AEC Qualified: N; Lp: 30; AEC Category: Q200; Value: 30uH; SizeZ_mm: 13.97; Ind_H: 30µH; SizeY_mm: 27.03; Ns1toNp: 0.375; Rsec1_ohm: 0.01; DCR_ohm: 0.022; SizeX_mm: 32.45
TP19-TP27 = 5019: Test Point, Miniature, SMT; Manufacturer: Keystone; CompType: Test Point Loop; U/M: EA
U2 = CMP-0081541-1: Automotive Grade 2.2-MHz Wide Input Non-synchronous Boost Controller, DSS0012C (WSON-12); Alternate PartNumber: LM51551QDSSTQ1; Alternate Manufacturer: Texas Instruments; SizeAreaWB_mm2: 12; SizeZ_mm: 0.8; SizeX_mm: 2; SizeY_mm: 3; SizeArea_mm2: 6; CompType: IC; AEC Qualified: Y; AEC Category: Q200
U3 = FOD817AS: Optocoupler, 5 kV, 80-160% CTR, SMT; Manufacturer: Fairchild Semiconductor; CTR (Min): 80%; CTR (Max): 160%; Voltage_Isolation_Vrms: 5000V
U4 = CMP-0084729-1: Programmable Shunt Regulator with Optimized Reference Current, DBZ0003A (SOT-23-3); Manufacturer: Texas Instruments; SizeY_mm: 3; SizeZ_mm: 1.12; SizeX_mm: 2.5; SizeAreaWB_mm2: 14; CompType: IC; AEC Qualified: N; AEC Category: Q200; SizeArea_mm2: 7.5

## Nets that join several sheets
RTN: PSIL024A_sch2 (10 pins), PSIL024A_sch3 (27 pins)
UVLO: PSIL024A_sch2 (R26.2), PSIL024A_sch3 (C33.1 R34.1 R37.2 U2.12)
VCIN: PSIL024A_sch2 (C16.1 U1.15), PSIL024A_sch3 (C39.1 D17.1 TP25.1)
VCOUT: PSIL024A_sch2 (C18.1 J5.1 U1.14), PSIL024A_sch3 (7 pins)
VDD: PSIL024A_sch1 (C8.1 D5.1 L1.2), PSIL024A_sch2 (7 pins), PSIL024A_sch3 (C21.2 C22.1 L7.1 R34.2)
VSS1: PSIL024A_sch1 (C8.2 D5.2 L3.2), PSIL024A_sch2 (J9.2 TP15.1)

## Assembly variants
001: not fitted D6 D7 D8 D9 FID1 FID2 FID3 FID4 FID5 FID6 R62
